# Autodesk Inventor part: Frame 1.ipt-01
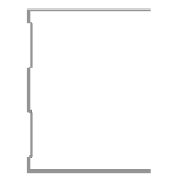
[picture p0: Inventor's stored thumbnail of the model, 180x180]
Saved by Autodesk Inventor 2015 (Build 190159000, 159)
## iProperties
Created: 2015-04
Part Number: Frame 1.ipt-01
Material: Aluminum 6061
Document SubType Name: Modeling
Standard: Unnamed
Designer: suporte
Language: en-US
Size Designation: (Unnamed 1)
Categories: <MemberInstance><Categories><Category DisplayName="Structural Shapes" InternalName="089c4875-fa83-4c05-b084-43b9cc11f5ed" Mnemonic="GRDR"><CategoryParameter Dis
Density: 2.7 g/cm^3
Appearance: Aluminum - Flat
IsCustomPart: 1
_CCFamilyMember: 1
_CCFamilyDisplayName: Frame 1
_FrameMemberDoc: Frame Member File
_Version: 15.0.0
_GetPNFromCC: 1
Author: suporte
G_L: 398,157 mm
G_W: 70,000 mm
G_H: 75,000 mm
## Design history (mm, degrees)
node "Start Plane"
node "End Plane"
sketch "Sketch"
  geometry: L1 (34.6, 37.5)-(34.6, 36.7); L2 (34.6, 36.7)-(-34.6, 36.7); L3 (-34.6, -36.7)-(34.6, -36.7); L4 (34.6, -36.7)-(34.6, -37.5); L5 (34.6, -37.5)-(-35.4, -37.5); L6 (-35.4, 37.5)-(34.6, 37.5); L7 (-34.6, 36.7)-(-34.6, 31.7); L8 (-34.6, 31.7)-(-33.4, 30.5); L9 (-33.4, 30.5)-(-33.4, 10.746); L10 (-33.4, 10.746)-(-34.6, 9.546); L11 (-34.6, 9.546)-(-34.6, -9.546); L12 (-34.6, -9.546)-(-33.4, -10.746); L13 (-33.4, -10.746)-(-33.4, -30.5); L14 (-33.4, -30.5)-(-34.6, -31.7); L15 (-34.6, -31.7)-(-34.6, -36.7); L16 (-35.4, -37.5)-(-35.4, -31.369); L17 (-35.4, -31.369)-(-34.2, -30.169); L18 (-34.2, -30.169)-(-34.2, -11.077); L19 (-34.2, -11.077)-(-35.4, -9.877); L20 (-35.4, -9.877)-(-35.4, 9.877); L21 (-35.4, 9.877)-(-34.2, 11.077); L22 (-34.2, 11.077)-(-34.2, 30.169); L23 (-34.2, 30.169)-(-35.4, 31.369); L24 (-35.4, 31.369)-(-35.4, 37.5); L25 (-35.4, 0)-(30.37, 0); 3 further points
  constraints: 50 end point, 10 point on line, 9 parallel, 5 perpendicular, 4 equal length, 3 midpoint, 3 vertical, 2 vertical alignment, 1 collinear, 1 horizontal, 1 horizontal alignment
  dimensions: "d3" = 0.8 distance of L1.start L1.end; "d5" = 75 distance between parallel lines of L5 L6; "d6" = 0.8 distance between parallel lines of L24 L7; "d7" = 0.8 distance between parallel lines of L8 L23; "d8" = 0.8 distance between parallel lines of L22 L9; "d9" = 0.8 distance between parallel lines of L17 L14; "d10" = 0.8 distance between parallel lines of L13 L18; "d11" = 0.8 distance between parallel lines of L12 L19; "d12" = 0.8 distance between parallel lines of L21 L10; "d13" = 5 distance of L2.end L7.end; "d15" = 135 deg angle of L9 L8; "d16" = 2 distance between parallel lines of L24 L9; "d17" = 70 distance of L6.start L1.start
extrude "Body" join sketch "Sketch" stored distance "d24" = 0.13; taper "d25" = 0 deg
node "Driven Length"
  sketch "Sketch8"
    geometry: L1 (0, 0)-(10, 0) reference
    constraints: 2 end point, 1 horizontal
  workplane "Work Plane6"
  sketch "Sketch9"
    geometry: L1 (-2, 0)-(12, 0) reference; L2 (-2, 398.157)-(12, 398.157) reference
    dimensions: "d27" = 398.15728 distance between parallel lines of L1 L2 (derived)
body "Solid1"
other parameters: "tamanho" = 398.15728, "G_OFFSET_START" = 0 [user parameter; used in 1 equation term], "G_OFFSET_END" = 0 [user parameter; used in 1 equation term], "d22" = 0 (computed from G_OFFSET_START), "d23" = 398.15728 (= tamanho + G_OFFSET_END), "G_L" = 398.15728 (= d27) [user parameter], "d32" = 90 deg
